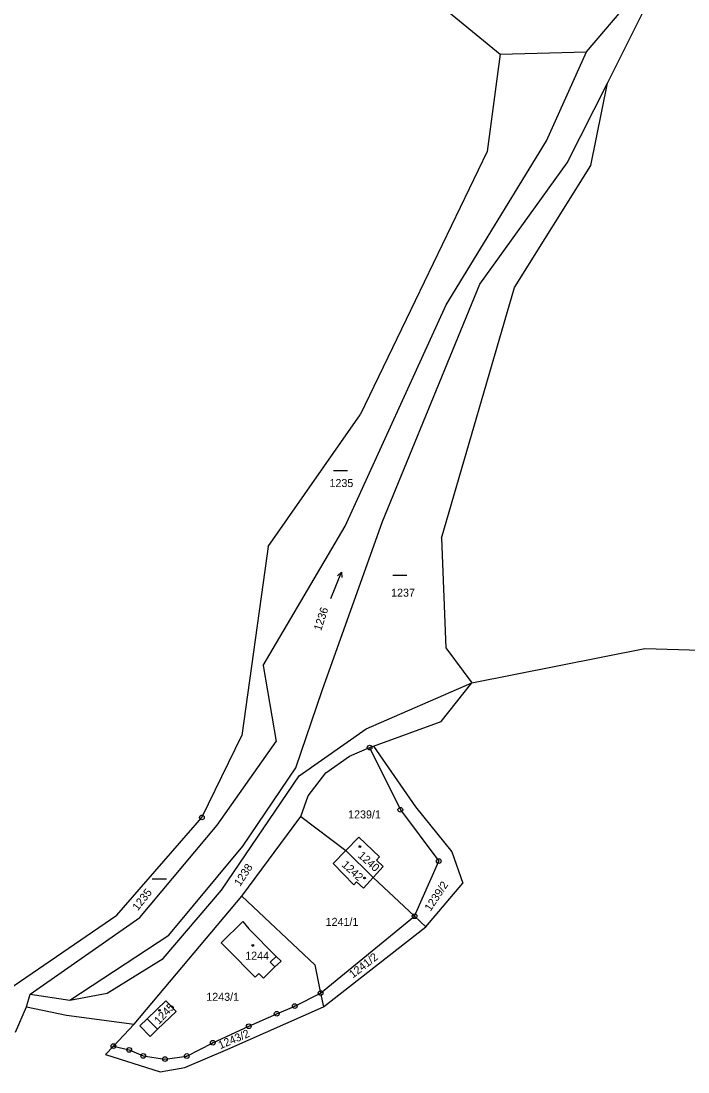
# Model space of a CAD drawing. Extents: x -779596 to -776743, y -1030330 to -1024513.
# Drawn here: x -779319.1 to -779177.4, y -1027546.7 to -1027323.5 of the extents above; entities that cross this region are included whole.
import ezdxf

# ---------------------------------------------------------------- set-up
doc = ezdxf.new("R2010")
doc.units = 0
for name, color, linetype in [('hranice parcel', 7, 'Continuous'), ('hranice vnitřní', 7, 'Continuous'), ('K_Ú_ hranice', 7, 'Continuous'), ('kultura', 7, 'Continuous'), ('Kód', 7, 'Continuous'), ('č_ parcel šipka', 7, 'Continuous'), ('č_pacel stav_', 7, 'Continuous'), ('č_parcel poz_', 7, 'Continuous')]:
    doc.layers.add(name, color=color, linetype=linetype)

msp = doc.modelspace()

# ---------------------------------------------------------------- linework, layer by layer
at = {"layer": 'hranice parcel'}
for points in [[(-779199.03, -1027330.02), (-779180.18, -1027307.81)], [(-779194.57, -1027336.66), (-779180.18, -1027307.81)], [(-779217.33, -1027330.47), (-779199.03, -1027330.02)], [(-779207.49, -1027348.91), (-779199.03, -1027330.02)], [(-779203.14, -1027353.59), (-779194.57, -1027336.66)], [(-779198.07, -1027354.17), (-779194.57, -1027336.66)], [(-779228.85, -1027383.72), (-779207.49, -1027348.91)], [(-779221.68, -1027379.32), (-779203.14, -1027353.59)], [(-779214.32, -1027380.03), (-779198.07, -1027354.17)], [(-779242.34, -1027429.75), (-779221.68, -1027379.32)], [(-779229.78, -1027433.29), (-779214.32, -1027380.03)], [(-779250.26, -1027430.72), (-779228.85, -1027383.72)], [(-779267.67, -1027460.33), (-779250.26, -1027430.72)], [(-779255.17, -1027465.63), (-779242.34, -1027429.75)], [(-779229.78, -1027433.29), (-779228.87, -1027456.58)], [(-779228.87, -1027456.58), (-779223.34, -1027464.01)], [(-779223.34, -1027464.01), (-779186.59, -1027456.72)], [(-779186.59, -1027456.72), (-779151.03, -1027457.76)], [(-779267.67, -1027460.33), (-779264.95, -1027476.43)], [(-779245.81, -1027473.79), (-779223.34, -1027464.01)], [(-779229.89, -1027472.23), (-779223.34, -1027464.01)], [(-779260.74, -1027482.03), (-779255.17, -1027465.63)], [(-779244.29, -1027477.44), (-779229.89, -1027472.23)], [(-779260.03, -1027483.78), (-779245.81, -1027473.79)], [(-779277.44, -1027494.25), (-779264.95, -1027476.43)], [(-779249.33, -1027479.57), (-779245.08, -1027477.77)], [(-779245.08, -1027477.77), (-779244.29, -1027477.44)], [(-779245.08, -1027477.77), (-779238.56, -1027490.97)], [(-779244.29, -1027477.44), (-779235.32, -1027490.33)], [(-779254.38, -1027483.15), (-779249.33, -1027479.57)], [(-779272.05, -1027498.72), (-779260.74, -1027482.03)], [(-779276.55, -1027508.01), (-779260.03, -1027483.78)], [(-779258.17, -1027487.97), (-779254.38, -1027483.15)], [(-779259.73, -1027492.41), (-779258.17, -1027487.97)], [(-779238.56, -1027490.97), (-779230.39, -1027501.86)], [(-779235.32, -1027490.33), (-779227.65, -1027499.89)], [(-779272.23, -1027509.34), (-779259.73, -1027492.41)], [(-779259.73, -1027492.41), (-779250.11, -1027499.64)], [(-779293.88, -1027513.83), (-779277.44, -1027494.25)], [(-779250.11, -1027499.64), (-779247.36, -1027496.81)], [(-779247.36, -1027496.81), (-779242.97, -1027500.96)], [(-779287.72, -1027517.56), (-779272.05, -1027498.72)], [(-779252.8, -1027502.39), (-779250.11, -1027499.64)], [(-779250.11, -1027499.64), (-779244.33, -1027505.34)], [(-779227.65, -1027499.89), (-779225.25, -1027506.53)], [(-779252.8, -1027502.39), (-779248.45, -1027506.94)], [(-779243.64, -1027501.7), (-779242.97, -1027500.96)], [(-779243.64, -1027501.7), (-779242.2, -1027503.01)], [(-779235.54, -1027513.57), (-779230.39, -1027501.86)], [(-779244.33, -1027505.34), (-779242.2, -1027503.01)], [(-779248.45, -1027506.94), (-779247.85, -1027506.29)], [(-779247.85, -1027506.29), (-779246.41, -1027507.61)], [(-779246.41, -1027507.61), (-779244.33, -1027505.34)], [(-779244.33, -1027505.34), (-779235.54, -1027513.57)], [(-779233.14, -1027515.82), (-779225.25, -1027506.53)], [(-779295.14, -1027536.52), (-779272.23, -1027509.34)], [(-779288.96, -1027522.58), (-779276.55, -1027508.01)], [(-779272.23, -1027509.34), (-779256.71, -1027523.87)], [(-779317.2, -1027530.15), (-779293.88, -1027513.83)], [(-779255.5, -1027529.91), (-779235.54, -1027513.57)], [(-779235.54, -1027513.57), (-779233.14, -1027515.82)], [(-779275.21, -1027520.64), (-779276.6, -1027519.2), (-779272.03, -1027514.7), (-779270.72, -1027516.22)], [(-779254.91, -1027532.83), (-779233.14, -1027515.82)], [(-779308.76, -1027531.43), (-779287.72, -1027517.56)], [(-779270.72, -1027516.22), (-779264.94, -1027522.09)], [(-779300.84, -1027529.89), (-779288.96, -1027522.58)], [(-779275.21, -1027520.64), (-779269.43, -1027526.51)], [(-779266.21, -1027523.34), (-779264.94, -1027522.09)], [(-779267.65, -1027526.7), (-779265.24, -1027524.33)], [(-779266.21, -1027523.34), (-779265.24, -1027524.33)], [(-779256.71, -1027523.87), (-779255.5, -1027529.91)], [(-779269.43, -1027526.51), (-779268.62, -1027525.71)], [(-779268.62, -1027525.71), (-779267.65, -1027526.7)], [(-779317.98, -1027532.83), (-779317.2, -1027530.15)], [(-779317.2, -1027530.15), (-779308.76, -1027531.43)], [(-779308.76, -1027531.43), (-779300.84, -1027529.89)], [(-779292.34, -1027535.34), (-779288.37, -1027531.53)], [(-779288.37, -1027531.53), (-779286.19, -1027533.79)], [(-779261, -1027532.66), (-779255.5, -1027529.91)], [(-779255.5, -1027529.91), (-779254.91, -1027532.83)], [(-779320.31, -1027538.18), (-779317.98, -1027532.83)], [(-779317.98, -1027532.83), (-779309.45, -1027534.56)], [(-779290.14, -1027537.58), (-779286.19, -1027533.79)], [(-779275.21, -1027541.8), (-779254.91, -1027532.83)], [(-779264.83, -1027534.3), (-779261, -1027532.66)], [(-779309.45, -1027534.56), (-779295.14, -1027536.52)], [(-779292.34, -1027535.34), (-779290.14, -1027537.58)], [(-779270.76, -1027536.94), (-779264.83, -1027534.3)], [(-779299.51, -1027541.15), (-779295.14, -1027536.52)], [(-779278.41, -1027540.44), (-779270.76, -1027536.94)], [(-779283.93, -1027543.26), (-779278.41, -1027540.44)], [(-779301.2, -1027542.94), (-779299.51, -1027541.15)], [(-779299.51, -1027541.15), (-779296.16, -1027541.97)], [(-779296.16, -1027541.97), (-779293.19, -1027543.24)], [(-779284.36, -1027545.68), (-779275.21, -1027541.8)], [(-779301.2, -1027542.94), (-779289.61, -1027546.65)], [(-779293.19, -1027543.24), (-779288.57, -1027543.91)], [(-779288.57, -1027543.91), (-779283.93, -1027543.26)], [(-779289.61, -1027546.65), (-779284.36, -1027545.68)]]:
    msp.add_lwpolyline(points, dxfattribs=at)
at = {"layer": 'hranice vnitřní'}
for points in [[(-779264.94, -1027522.09), (-779263.9, -1027523.15)], [(-779265.24, -1027524.33), (-779263.9, -1027523.15)], [(-779293.88, -1027536.83), (-779292.34, -1027535.34)], [(-779293.88, -1027536.83), (-779291.71, -1027539.09)], [(-779291.71, -1027539.09), (-779290.14, -1027537.58)]]:
    msp.add_lwpolyline(points, dxfattribs=at)
at = {"layer": 'K_Ú_ hranice'}
for points in [[(-779244.03, -1027308.52), (-779217.33, -1027330.47)], [(-779217.33, -1027330.47), (-779217.97, -1027335.25)], [(-779217.97, -1027335.25), (-779220.11, -1027351.19)], [(-779220.11, -1027351.19), (-779237.31, -1027386.83)], [(-779237.31, -1027386.83), (-779247.08, -1027407.07)], [(-779266.61, -1027435.06), (-779247.08, -1027407.07)], [(-779266.61, -1027435.06), (-779266.9, -1027437.13)], [(-779266.9, -1027437.13), (-779272.2, -1027475.2)], [(-779280.7, -1027492.6), (-779272.2, -1027475.2)], [(-779298.76, -1027513.35), (-779280.7, -1027492.6)], [(-779327.16, -1027532.71), (-779298.76, -1027513.35)]]:
    msp.add_lwpolyline(points, dxfattribs=at)
at = {"layer": 'kultura'}
for points in [[(-779252.77, -1027418.89), (-779249.77, -1027418.89)], [(-779253.309, -1027446.087), (-779251.091, -1027440.513)], [(-779251.926, -1027441.257), (-779251.091, -1027440.513), (-779250.996, -1027441.627)], [(-779240.15, -1027441.17), (-779237.15, -1027441.17)], [(-779291.26, -1027505.62), (-779288.26, -1027505.62)]]:
    msp.add_lwpolyline(points, dxfattribs=at)
for centre in [(-779247.15, -1027498.78), (-779246.16, -1027505.46), (-779269.9, -1027519.78), (-779289.71, -1027533.55)]:
    msp.add_circle(centre, 0.175, dxfattribs=at)
at = {"layer": 'Kód'}
for centre, radius in [((-779245.08, -1027477.77), 0.5), ((-779245.08, -1027477.77), 0.032), ((-779238.56, -1027490.97), 0.5), ((-779238.56, -1027490.97), 0.032), ((-779280.7, -1027492.6), 0.5), ((-779280.7, -1027492.6), 0.032), ((-779230.39, -1027501.86), 0.5), ((-779230.39, -1027501.86), 0.032), ((-779235.54, -1027513.57), 0.5), ((-779235.54, -1027513.57), 0.032), ((-779255.5, -1027529.91), 0.5), ((-779255.5, -1027529.91), 0.032), ((-779264.83, -1027534.3), 0.5), ((-779261, -1027532.66), 0.5), ((-779261, -1027532.66), 0.032), ((-779264.83, -1027534.3), 0.032), ((-779270.76, -1027536.94), 0.5), ((-779270.76, -1027536.94), 0.032), ((-779299.51, -1027541.15), 0.5), ((-779278.41, -1027540.44), 0.5), ((-779278.41, -1027540.44), 0.032), ((-779299.51, -1027541.15), 0.032), ((-779296.16, -1027541.97), 0.5), ((-779296.16, -1027541.97), 0.032), ((-779293.19, -1027543.24), 0.5), ((-779283.93, -1027543.26), 0.5), ((-779293.19, -1027543.24), 0.032), ((-779288.57, -1027543.91), 0.5), ((-779288.57, -1027543.91), 0.032), ((-779283.93, -1027543.26), 0.032)]:
    msp.add_circle(centre, radius, dxfattribs=at)

# ---------------------------------------------------------------- texts
at = {"layer": 'č_ parcel šipka'}
msp.add_text('1235', height=1.7, rotation=51.90041, dxfattribs=at).set_placement((-779294.333, -1027512.53))
at = {"layer": 'č_pacel stav_'}
for s, rotation, p in [('1240', 318.30253, (-779247.698, -1027500.894)), ('1242', 317.50252, (-779251.138, -1027502.828)), ('1245', 46.60037, (-779289.827, -1027536.658))]:
    msp.add_text(s, height=1.7, rotation=rotation, dxfattribs=at).set_placement(p)
msp.add_text('1244', height=1.7, dxfattribs=at).set_placement((-779271.51, -1027522.81))
at = {"layer": 'č_parcel poz_'}
for s, p in [('1235', (-779253.61, -1027422.43)), ('1237', (-779240.52, -1027445.71)), ('1239/1', (-779249.65, -1027492.8)), ('1241/1', (-779254.43, -1027515.62)), ('1243/1', (-779279.78, -1027531.54))]:
    msp.add_text(s, height=1.7, dxfattribs=at).set_placement(p)
for s, rotation, p in [('1236', 72.00057, (-779255.398, -1027453.088)), ('1238', 56.80045, (-779272.597, -1027507.354)), ('1239/2', 56.30045, (-779232.145, -1027512.663)), ('1241/2', 37.8003, (-779248.635, -1027526.82)), ('1243/2', 23.10018, (-779276.805, -1027541.828))]:
    msp.add_text(s, height=1.7, rotation=rotation, dxfattribs=at).set_placement(p)

doc.saveas('drawing.dxf')
